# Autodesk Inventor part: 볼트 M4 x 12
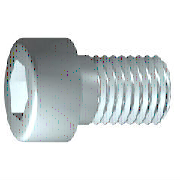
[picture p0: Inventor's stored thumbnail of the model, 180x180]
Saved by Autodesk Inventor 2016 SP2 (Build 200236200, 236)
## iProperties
IsCustomPart: 0
Created: 2012-02
Part Number: 볼트 M4 x 12
Material: 스테인리스강
Description: 6각 소켓 머리 캡 나사
Document SubType Name: Modeling
Standard: ISO 4762
Designer: mduedu
Standard Revision: Fourth edition 2004-03-01
Standards Organization: ISO
Language: ko-KR
Size Designation: M4 x 12
Categories: <MemberInstance><Categories><Category DisplayName="조임쇠" InternalName="e4da775c-781d-43d5-af7c-5136215cf5a6" Mnemonic="FSTN"><Category DisplayName="볼트" InternalN
Density: 8.08 g/cm^3
Appearance: 반광택
Author: mduedu
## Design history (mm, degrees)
sketch "스케치1"
  geometry: L1 (-1, 0)-(12, 0); L2 (12, 0)-(12, 2); L3 (12, 2)-(1.75, 2); L4 (1.75, 2)-(1.32, 2); L5 (1.32, 2)-(0, 2); L6 (0, 2)-(0, 3.5); L7 (0, 3.5)-(-4, 3.5); L8 (-4, 3.5)-(-4, 1.732); L9 (-4, 1.732)-(-2, 1.732); L10 (-2, 1.732)-(-1, 0); L11 (-7.2, 0)-(15.2, 0) reference; L12 (0, -0.7)-(0, 4.2) reference; L13 (1.75, 2)-(0, 2)
  constraints: 22 end point, 6 parallel, 2 collinear, 2 perpendicular, 1 horizontal, 1 point on line
  dimensions: "d1" = 10.25 distance from line of L3.end L2 (= GEL); "d2" = 0.42952 distance of L4.end L3.end (computed from GAL); "d3" = 4 distance between parallel lines of L8 L6 (= KOH); "d4" = 2 distance of L8.end L9.end (= INTI); "d5" = 60 deg angle of L10 L1; "d6" = 4 diameter of L3 L1 (= GD); "d7" = 4 diameter of L5 L1 (= BDM); "d8" = 3.4641 diameter of L9 L1 (= 1.1547 x SW); "d9" = 7 diameter of L7 L1 (= KOD); "d26" = 12 distance between parallel lines of L12 L2 (= NLG)
revolve "본체" sketch "스케치1" stored, may be unused: angle "d10" = 90 deg
sketch "스케치2"
  geometry: L1 (0, -4.9)-(0, 4.9) reference; L2 (-4.9, 0)-(4.9, 0) reference; L3 (1.732, 0)-(0.866, -1.5); L4 (0.866, -1.5)-(-0.866, -1.5); L5 (-0.866, -1.5)-(-1.732, 0); L6 (-1.732, 0)-(-0.866, 1.5); L7 (-0.866, 1.5)-(0.866, 1.5); L8 (0.866, 1.5)-(1.732, 0); 2 further points
  constraints: 12 end point, 1 coincident, 1 horizontal alignment, 1 point on line, 12 other
extrude "슬롯" join sketch "스케치2" stored distance "d11" = 10; taper "d12" = 0 deg
workplane "Work Plane1"
fillet "Fillet2" dims "d30" = 0.1 (= R)
body "Solid1"
fillet "모깎기1" dims "d17" = 0.4 (= RR)
feature "스레드" dims "d13" = 10.25 (= GEL), "d14" = 0
chamfer "모따기1" distance "d15" = 0.42941 (= -0.5 x SPD + 0.5 x GD); stored, may be unused: second distance "d16" = 0.42941 (= GUL), angle "d27" = 45 deg
other parameters: "GD" = 4 [user parameter; used in 2 equation terms], "NLG" = 12 [user parameter; used in 1 equation term], "GEL" = 10.25 [user parameter; used in 2 equation terms], "KOD" = 7 [user parameter; used in 1 equation term], "KOH" = 4 [user parameter; used in 1 equation term], "INTI" = 2 [user parameter; used in 1 equation term], "GAL" = 0.42941 (= 0.61345 x PTC) [user parameter; used in 1 equation term], "GUL" = 0.42941 (= 0.61345 x PTC) [user parameter; used in 1 equation term], "BDM" = 4 (= NND) [user parameter; used in 1 equation term], "SW" = 3 [user parameter; used in 2 equation terms], "RR" = 0.4 [user parameter; used in 1 equation term], "SPD" = 3.14117 (= NND - 1.2269 x PTC) [user parameter; used in 1 equation term], "d19" = 0, "d28" = 0, "d29" = 0, "R" = 0.1 [user parameter; used in 1 equation term], "TOA" = 30 deg [user parameter], "GD1" = 3.14117 (= THREADDIA - 1.2269 x PTC) [user parameter], "THREADDIA" = 4 [user parameter; used in 1 equation term], "FAWI" = 45 deg [user parameter], "TPU" = 14.28571 (computed from PTC) [user parameter], "PTC" = 0.7 [user parameter; used in 5 equation terms], "NND" = 4 [user parameter; used in 2 equation terms], "E0" = 3.465 (= 1.155 x SW) [user parameter]
